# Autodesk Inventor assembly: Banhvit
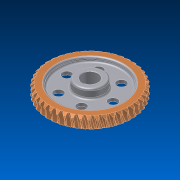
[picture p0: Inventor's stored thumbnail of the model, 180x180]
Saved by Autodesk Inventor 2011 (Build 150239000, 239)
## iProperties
Created: 2011-06
Part Number: Banhvit
Document SubType Name: Assembly
Designer: 904Chiaki
Author: 904Chiaki
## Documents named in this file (3)
- E:\2.FINISH\DOAN_CTM_final\Banhvit.iam
- E:\2.FINISH\DOAN_CTM_final\Thanbanhrang.ipt
- E:\2.FINISH\DOAN_CTM_final\Vanhbanhrang.ipt
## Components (2 placed, 1 different names)
1. Worm Gear:1 — Mate:1, Mate:2
2. Worm Gear:2 — Mate:1, Mate:2
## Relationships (2: Mate 2)
- Mate:1: Worm Gear:1 ↔ Worm Gear:2
- Mate:2: Worm Gear:1 ↔ Worm Gear:2
